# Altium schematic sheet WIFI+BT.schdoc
size 297 x 209 mm; Symbol: Drawing-Symbol_A4; Company: 嘉立创EDA; Version: V1.0; Page Size: A4; @Project Name: A113 Android MircroPhone; @Page Count: 5; @Update Date: 2025-12-04; @Create Date: 2025-12-04; @Schematic Name: Schematic1; @Page No: 5; @Page Name: WIFI+BT; @Create Time: 23:39:23; @Update Time: 23:39:41; Border: 1; Width: 1170; Height: 825; Region Start: 1; X Region Count: 6; Y Region Count: 4; Blade Width: 10; Title Block Position: 3; @Board Name: Board1; Device: Drawing-Symbol_A4
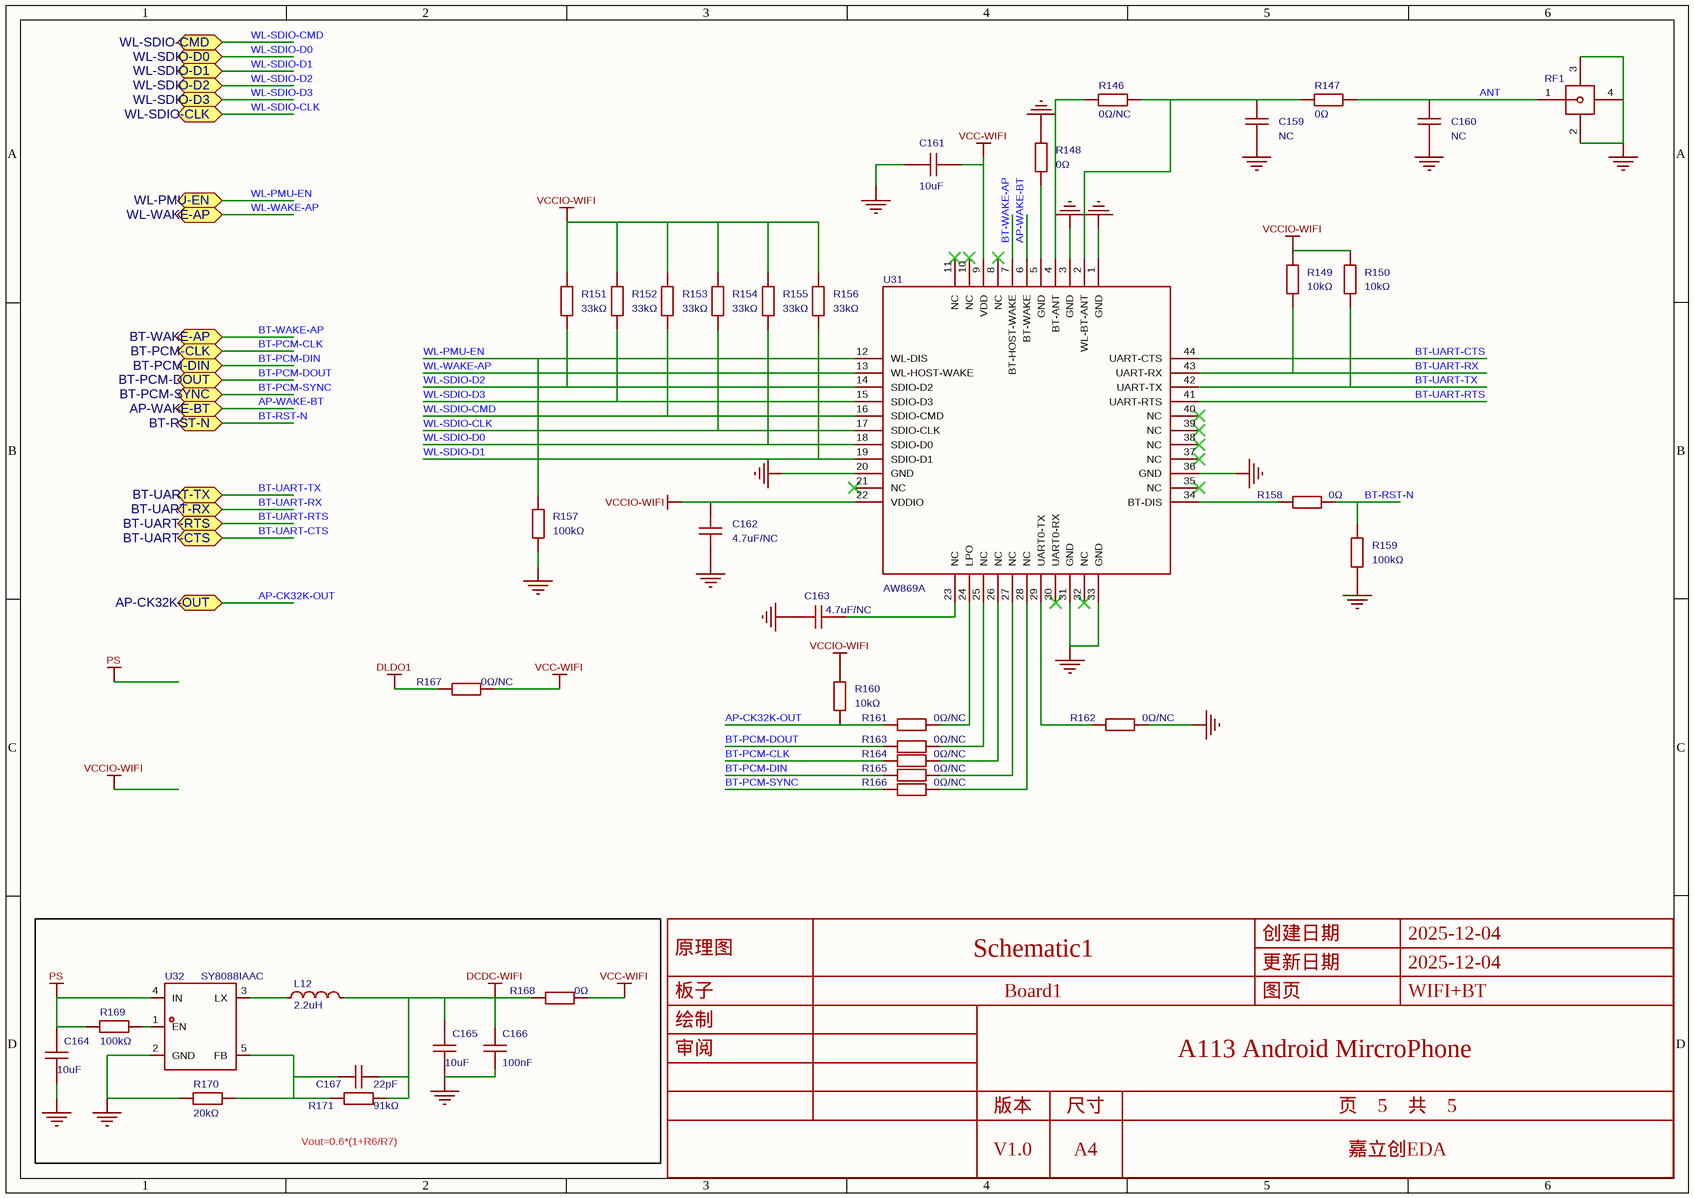
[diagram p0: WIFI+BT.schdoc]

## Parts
C159  NC  [C0402]
C160  NC  [C0402]
C161  10uF  [C0603]
C162  4.7uF/NC  [C0402]
C163  4.7uF/NC  [C0402]
C164  10uF  [C0603]
C165  10uF  [C0603]
C166  100nF  [C0402]
C167  22pF  [C0402]
L12  2.2uH  [IND-SMD_L3.0-W3.0]
R146  0Ω/NC  [R0402]
R147  0Ω  [R0402]
R148  0Ω  [R0402]
R149  10kΩ  [R0402]
R150  10kΩ  [R0402]
R151  33kΩ  [R0402]
R152  33kΩ  [R0402]
R153  33kΩ  [R0402]
R154  33kΩ  [R0402]
R155  33kΩ  [R0402]
R156  33kΩ  [R0402]
R157  100kΩ  [R0402]
R158  0Ω  [R0402]
R159  100kΩ  [R0402]
R160  10kΩ  [R0402]
R161  0Ω/NC  [R0402]
R162  0Ω/NC  [R0402]
R163  0Ω/NC  [R0402]
R164  0Ω/NC  [R0402]
R165  0Ω/NC  [R0402]
R166  0Ω/NC  [R0402]
R167  0Ω/NC  [R0402]
R168  0Ω  [R0402]
R169  100kΩ  [R0402]
R170  20kΩ  [R0402]
R171  91kΩ  [R0402]
RF1  KH-IPEX3-2020  [IPEX-SMD_4P-L1.7-W1.7-LS2.0-L]  (value not drawn)
U31  (no value)  [QFN-44_L12.0-W12.0-P0.90-AW869A]
U32  SY8088IAAC  [SOT-23-5_L3.0-W1.7-P0.95-LS2.8-BL]

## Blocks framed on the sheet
Vout=0.6*(1+R6/R7): C164-C167 L12 R168-R171 U32

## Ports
AP-CK32K-OUT (bidir), AP-WAKE-BT (bidir), BT-PCM-CLK (bidir), BT-PCM-DIN (bidir), BT-PCM-DOUT (bidir), BT-PCM-SYNC (bidir), BT-RST-N (bidir), BT-UART-CTS (bidir), BT-UART-RTS (bidir), BT-UART-RX (bidir), BT-UART-TX (bidir), BT-WAKE-AP (bidir), WL-PMU-EN (bidir), WL-SDIO-CLK (bidir), WL-SDIO-CMD (bidir), WL-SDIO-D0 (bidir), WL-SDIO-D1 (bidir), WL-SDIO-D2 (bidir), WL-SDIO-D3 (bidir), WL-WAKE-AP (bidir)

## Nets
DCDC-WIFI: C165.2 C166.1 C167.2 L12.2 R168.1 R171.2
DLDO1: R167.1
GND: C159.1 C160.1 C161.1 C162.1 C163.1 C164.1 C165.1 C166.2 R148.2 R157.1 R159.1 R162.2 R170.1 RF1.2 RF1.3 RF1.4 U31.1(GND) U31.3(GND) U31.20(GND) U31.31(GND) U31.33(GND) U31.36(GND) U32.2(GND)
PS: C164.2 R169.2 U32.4(IN)
VCC-WIFI: C161.2 R167.2 R168.2 U31.9(VDD)
VCCIO-WIFI: C162.2 R149.2 R150.2 R151.2 R152.2 R153.2 R154.2 R155.2 R156.2 R160.2 U31.22(VDDIO)
ANT: C160.2 R147.1 RF1.1
AP-CK32K-OUT: R160.1 R161.1 ; port AP-CK32K-OUT
AP-WAKE-BT: U31.6(BT-WAKE) ; port AP-WAKE-BT
BT-PCM-CLK: R164.1 ; port BT-PCM-CLK
BT-PCM-DIN: R165.1 ; port BT-PCM-DIN
BT-PCM-DOUT: R163.1 ; port BT-PCM-DOUT
BT-PCM-SYNC: R166.1 ; port BT-PCM-SYNC
BT-RST-N: R158.2 R159.2 ; port BT-RST-N
BT-UART-CTS: U31.44(UART-CTS) ; port BT-UART-CTS
BT-UART-RTS: U31.41(UART-RTS) ; port BT-UART-RTS
BT-UART-RX: R149.1 U31.43(UART-RX) ; port BT-UART-RX
BT-UART-TX: R150.1 U31.42(UART-TX) ; port BT-UART-TX
BT-WAKE-AP: U31.7(BT-HOST-WAKE) ; port BT-WAKE-AP
WL-PMU-EN: R157.2 U31.12(WL-DIS) ; port WL-PMU-EN
WL-SDIO-CLK: R154.1 U31.17(SDIO-CLK) ; port WL-SDIO-CLK
WL-SDIO-CMD: R153.1 U31.16(SDIO-CMD) ; port WL-SDIO-CMD
WL-SDIO-D0: R155.1 U31.18(SDIO-D0) ; port WL-SDIO-D0
WL-SDIO-D1: R156.1 U31.19(SDIO-D1) ; port WL-SDIO-D1
WL-SDIO-D2: R151.1 U31.14(SDIO-D2) ; port WL-SDIO-D2
WL-SDIO-D3: R152.1 U31.15(SDIO-D3) ; port WL-SDIO-D3
WL-WAKE-AP: U31.13(WL-HOST-WAKE) ; port WL-WAKE-AP
NetC159_2: C159.2 R146.1 R147.2 U31.2(WL-BT-ANT)
NetC163_2: C163.2 U31.23(NC)
NetC167_1: C167.1 R170.2 R171.1 U32.5(FB)
NetL12_1: L12.1 U32.3(LX)
NetR146_2: R146.2 U31.4(BT-ANT)
NetR148_1: R148.1 U31.5(GND)
NetR158_1: R158.1 U31.34(BT-DIS)
NetR161_2: R161.2 U31.24(LPO)
NetR162_1: R162.1 U31.29(UART0-TX)
NetR163_2: R163.2 U31.25(NC)
NetR164_2: R164.2 U31.26(NC)
NetR165_2: R165.2 U31.27(NC)
NetR166_2: R166.2 U31.28(NC)
NetR169_1: R169.1 U32.1(EN)

Not connected (* = marked no-connect by the designer): U31 8(NC)* 10(NC)* 11(NC)* 21(NC)* 30(UART0-RX)* 32(NC)* 35(NC)* 37(NC)* 38(NC)* 39(NC)* 40(NC)*

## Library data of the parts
C159 C160 = CL05C330JB5NNNC: 容值:33pF;精度:±5%;额定电压:50V;材质(温度系数):C0G;; Manufacturer: SAMSUNG(三星); Standardization Check: false; AddInBom: yes; ModelId: 36a51122f27c49738f86b3bfa98863e0; ModelName: C0402_L1.0-W0.5-H0.5; ModelTransform: 39.37,19.685,0,0,0,0,0,0,0; Tolerance: ±5%; Voltage Rated: 50V; Temperature Coefficient: C0G
C161 C164 C165 = CL10A106KP8NNNC: 容值:10uF;精度:±10%;额定电压:10V;材质(温度系数):X5R;; Manufacturer: SAMSUNG(三星); AddInBom: yes; ModelId: ac125912035d415993ca9572d50418b1; ModelName: C0603_L1.6-W0.8-H0.8; ModelTransform: 62.992,31.496,0,0,0,0,0,0,0; Tolerance: ±10%; Voltage Rated: 10V; Temperature Coefficient: X5R
C162 C163 = CL05A475MQ5NRNC: 容值:4.7uF;精度:±20%;额定电压:6.3V;材质(温度系数):X5R;; Manufacturer: SAMSUNG(三星); Standardization Check: false; Symbol: CL05A475MQ5NRNC_C307423; AddInBom: yes; ModelId: 36a51122f27c49738f86b3bfa98863e0; ModelName: C0402_L1.0-W0.5-H0.5; ModelTransform: 39.37,19.685,0,0,0,0,0,0,0; Tolerance: ±20%; Voltage Rated: 6.3V; Temperature Coefficient: X5R
C166 = CL05B104KO5NNNC: 容值:100nF;精度:±10%;额定电压:16V;材质(温度系数):X7R;; Manufacturer: SAMSUNG(三星); AddInBom: yes; ModelId: 36a51122f27c49738f86b3bfa98863e0; ModelName: C0402_L1.0-W0.5-H0.5; ModelTransform: 39.37,19.685,0,0,0,0,0,0,0; Tolerance: ±10%; Voltage Rated: 16V; Temperature Coefficient: X7R
C167 = CL05C220JB5NNNC: 容值:22pF;精度:±5%;额定电压:50V;材质(温度系数):C0G;; Manufacturer: SAMSUNG(三星); Symbol: CL10C220JB8NNNC; AddInBom: yes; ModelId: 36a51122f27c49738f86b3bfa98863e0; ModelName: C0402_L1.0-W0.5-H0.5; ModelTransform: 39.37,19.685,0,0,0,0,0,0,0; Tolerance: ±5%; Voltage Rated: 50V; Temperature Coefficient: C0G
L12 = SWPA3015S2R2MT: 电感值:2.2uH;精度:±20%;额定电流:2A;; Manufacturer: Sunlord(顺络); AddInBom: yes; ModelId: 67451da4701445baa335959290a67a23; ModelName: IND-SMD_L3.0-W3.0-H1.5; ModelTransform: 118.11,118.8974,0,90,0,0,0,0,0; Tolerance: ±20%; Rated Current: 2A
R146 R161-R167 = RC0402JR-070RL: 电阻类型:厚膜电阻;阻值:0Ω;精度:-;功率:62.5mW;; Manufacturer: YAGEO(国巨); Standardization Check: false; AddInBom: yes; ModelId: 671aefced39d4c318694bba8bd8efd39; ModelName: R0402_L1.0-W0.5-H0.5; ModelTransform: 39.37,19.685,0,0,0,0,0,0.0005,0; Power(Watts): 62.5mW; Overload Voltage (Max): 50V
R147 R168 = 0402WGF0000TCE: 电阻类型:厚膜电阻;阻值:0Ω;精度:±1%;功率:62.5mW;; Manufacturer: UNI-ROYAL(厚声); Symbol: RC0402JR-070RL; AddInBom: yes; ModelId: 671aefced39d4c318694bba8bd8efd39; ModelName: R0402_L1.0-W0.5-H0.5; ModelTransform: 39.37,19.685,0,0,0,0,0,0.0005,0; Tolerance: ±1%; Power(Watts): 62.5mW; Temperature Coefficient: ±800ppm/℃; Overload Voltage (Max): 50V
R148 R158 = RC0402JR-070RL: 电阻类型:厚膜电阻;阻值:0Ω;精度:-;功率:62.5mW;; Manufacturer: YAGEO(国巨); AddInBom: yes; ModelId: 671aefced39d4c318694bba8bd8efd39; ModelName: R0402_L1.0-W0.5-H0.5; ModelTransform: 39.37,19.685,0,0,0,0,0,0.0005,0; Power(Watts): 62.5mW; Overload Voltage (Max): 50V
R149 R150 R160 = RC0402FR-0710KL: 电阻类型:厚膜电阻;阻值:10kΩ;精度:±1%;功率:62.5mW;; Manufacturer: YAGEO(国巨); AddInBom: yes; ModelId: 671aefced39d4c318694bba8bd8efd39; ModelName: R0402_L1.0-W0.5-H0.5; ModelTransform: 39.37,19.685,0,0,0,0,0,0.0005,0; Tolerance: ±1%; Power(Watts): 62.5mW; Temperature Coefficient: ±100ppm/℃; Overload Voltage (Max): 50V
R151-R156 = RC0402FR-0733KL: 电阻类型:厚膜电阻;阻值:33kΩ;精度:±1%;功率:62.5mW;; Manufacturer: YAGEO(国巨); AddInBom: yes; ModelId: 671aefced39d4c318694bba8bd8efd39; ModelName: R0402_L1.0-W0.5-H0.5; ModelTransform: 39.37,19.685,0,0,0,0,0,0.0005,0; Tolerance: ±1%; Power(Watts): 62.5mW; Temperature Coefficient: ±100ppm/℃; Overload Voltage (Max): 50V
R157 R159 R169 = 0402WGF1003TCE: 电阻类型:厚膜电阻;阻值:100kΩ;精度:±1%;功率:62.5mW;; Manufacturer: UNI-ROYAL(厚声); AddInBom: yes; ModelId: 671aefced39d4c318694bba8bd8efd39; ModelName: R0402_L1.0-W0.5-H0.5; ModelTransform: 39.37,19.685,0,0,0,0,0,0.0005,0; Tolerance: ±1%; Power(Watts): 62.5mW; Temperature Coefficient: ±100ppm/℃; Overload Voltage (Max): 50V
R170 = RC0402FR-0720KL: 电阻类型:厚膜电阻;阻值:20kΩ;精度:±1%;功率:62.5mW;; Manufacturer: YAGEO(国巨); AddInBom: yes; ModelId: 671aefced39d4c318694bba8bd8efd39; ModelName: R0402_L1.0-W0.5-H0.5; ModelTransform: 39.37,19.685,0,0,0,0,0,0.0005,0; Tolerance: ±1%; Power(Watts): 62.5mW; Temperature Coefficient: ±100ppm/℃; Overload Voltage (Max): 50V
R171 = RC0402FR-0791KL: 电阻类型:厚膜电阻;阻值:91kΩ;精度:±1%;功率:62.5mW;; Manufacturer: YAGEO(国巨); Symbol: RC0603FR-0791KL; AddInBom: yes; ModelId: 671aefced39d4c318694bba8bd8efd39; ModelName: R0402_L1.0-W0.5-H0.5; ModelTransform: 39.37,19.685,0,0,0,0,0,0.0005,0; Tolerance: ±1%; Power(Watts): 62.5mW; Temperature Coefficient: ±100ppm/℃; Overload Voltage (Max): 50V
RF1 = KH-IPEX3-2020: 连接器类型:板端;射频系列:IPEX;接口类型:内针;端口数量:1;阻抗:-;频率-最大值:6GHz;样式:-;接口直径:1.4mm;接口长度/高度:-;工作温度范围:-;; Manufacturer: kinghelm(金航标); AddInBom: yes; ModelId: f012486134a24e60bd302ae5be7fc697; ModelTransform: 78.74,78.74,0,0,0,0,0.98,0,0; Connector Type: 板端; RF Series: IPEX; Interface Type: 内针; Number of Ports: 1; Frequency-Max: 6GHz; Interface Diameter: 1.4mm
U31 = AW869A: 这是一款双频WiFi6、BT5.2的模块，支持1*1 IEEE 802.11a/b/g/n/ac/ax WLAN 标准和 BT 5.2 的组合解决方案，可实现 WLAN/BT 和低能耗技术的无缝集成。; Standardization Check: false; AddInBom: yes
U32 = SY8088IAAC: Manufacturer: silergy(矽力杰); AddInBom: yes; ModelId: 0a2a1b8f50944f73965918ad6e5fe167; ModelName: SOT-23-5_L2.9-W1.6-H1.1-LS2.8-P0.95; ModelTransform: 118.60433,114.173,0,90,0,0,0.0005,0.0005,0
